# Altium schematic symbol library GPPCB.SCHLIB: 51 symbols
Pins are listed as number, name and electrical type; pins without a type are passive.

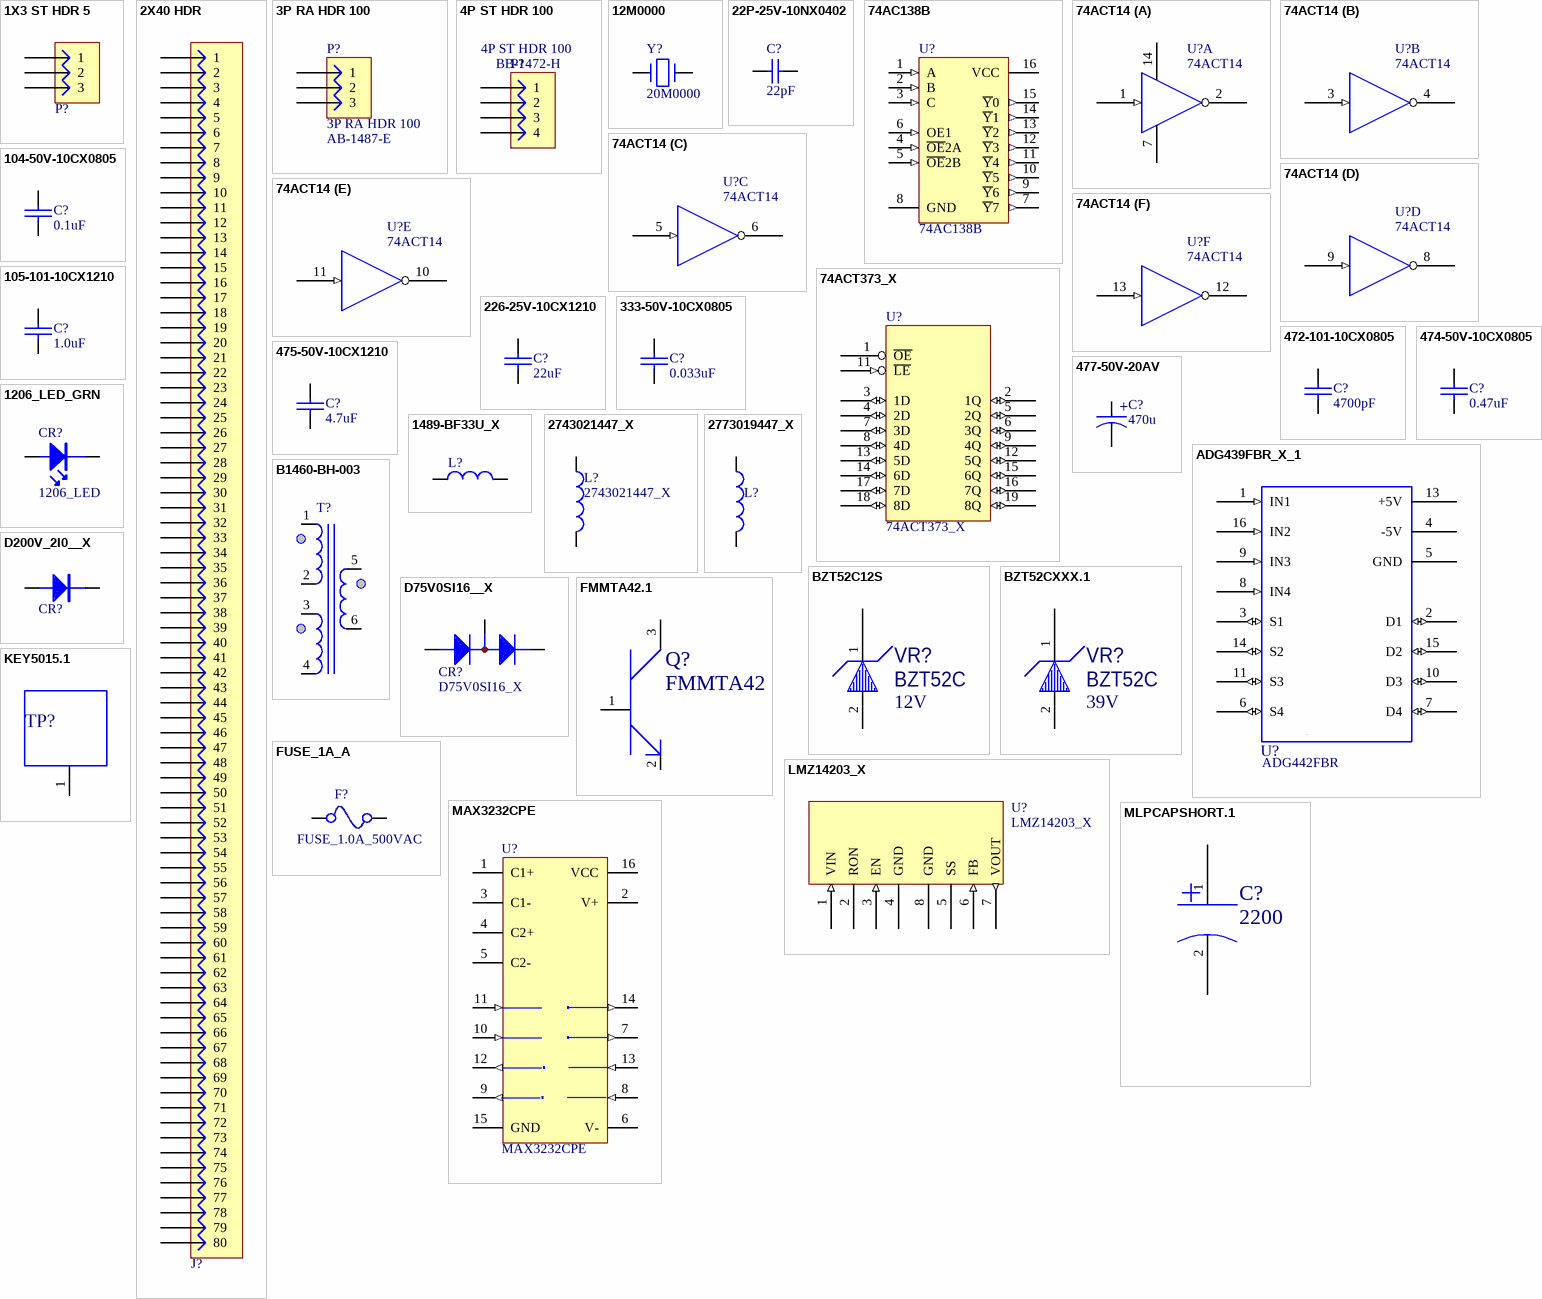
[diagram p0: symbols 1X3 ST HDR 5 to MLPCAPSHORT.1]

## 1X3 ST HDR 5
designator P?  (value not drawn)
HEADER, 3 PIN, ST, 5mm CTRS; AREA: 0.475
footprint H(JV01) (3P 30A ST PCB FEMALE)
pins: 1, 2, 3

## 2X40 HDR
designator J?  (value not drawn)
HEADER, 80 PIN; NAME: 80 PIN HEADER
footprint H2X40 (Footprint not found)
pins: 1, 2, 3, 4, 5, 6, 7, 8, 9, 10, 11, 12, 13, 14, 15, 16, 17, 18, 19, 20, 21, 22, 23, 24, 25, 26, 27, 28, 29, 30, 31, 32, 33, 34, 35, 36, 37, 38, 39, 40, 41, 42, 43, 44, 45, 46, 47, 48, 49, 50, 51, 52, 53, 54, 55, 56, 57, 58, 59, 60, 61, 62, 63, 64, 65, 66, 67, 68, 69, 70, 71, 72, 73, 74, 75, 76, 77, 78, 79, 80

## 3P RA HDR 100
designator P?  AMETEK PART NO: AB-1487-E  (hidden comment: 3P RA HDR 100)
HEADER, 3 PIN, RA, 0.100 CTRS; AREA: 0.15; DESIGNER: GTN 3/20/08
footprint H3RA100
pins: 1, 2, 3

## 4P ST HDR 100
designator P?  AMETEK PART NO: BB-1472-H  (hidden comment: 4P ST HDR 100)
HEADER, 4 PIN, ST, 0.100 CTRS
footprint SIP4
pins: 1, 2, 3, 4

## 12M0000
designator Y?, comment 20M0000
12.0000 MHZ XTAL; AMETEK PART NO: CB-1535-S; AMETEK DESCRIPTION: 12M0000
footprint XTAL3_I (XTAL_CC7V-T1A)
pins: 1, 2

## 22P-25V-10NX0402
designator C?  value 22pF  (hidden comment: 22P-25V-10NX0402)
CAP CERAMIC 22PF 25V 10% COG 0402; AMETEK PART NO: B1605-082; AREA: 0.0017; CHECKER: RSK 8/7/13; DESIGNER: GTN  10/31/11
footprint 0402/0.6/N (0402/N to 0402/0.6/N)
pins: 1, 2
1 alternate drawing of the same symbol

## 74AC138B
designator U?
3-to-8 Line Decoder Inverting
footprint DIP16 (DIP; 16 Leads; Row Spacing 7.62 mm; Pitch 2.54 mm)
3D model DIP16 (DIP; 16 Leads; Row Spacing 7.62 mm; Pitch 2.54 mm)
signal-integrity model 74AC138B
pins: 1 A (in), 2 B (in), 3 C (in), 4 ~{OE}2A (in), 5 ~{OE}2B (in), 6 OE1 (in), 7 ~{Y}7 (out), 8 GND (power), 9 ~{Y}6 (out), 10 ~{Y}5 (out), 11 ~{Y}4 (out), 12 ~{Y}3 (out), 13 ~{Y}2 (out), 14 ~{Y}1 (out), 15 ~{Y}0 (out), 16 VCC (power)

## 74ACT14
designator U?
IC, CMOS HEX INVERTER , DIP14; AMETEK PART NO: AB-1503-G; AREA: .263; DESIGNER: LEGACY PART 2/9/04 GTN
footprint DIP14
part A pins: 1 (in), 2, 7 (power), 14 (power)
part B pins: 3 (in), 4
part C pins: 5 (in), 6
part D pins: 8, 9 (in)
part E pins: 10, 11 (in)
part F pins: 12, 13 (in)

## 74ACT373_X
designator U?
IC, LATCH, OCTAL TRANSPARENT, TRISTATE; AMETEK PART NO: B1579-JP-001; AREA: 0.240; CHECKER: LEGACY PART
footprint SOL-20/N
pins: 1 ~{OE}, 2 1Q (io), 3 1D (io), 4 2D (io), 5 2Q (io), 6 3Q (io), 7 3D (io), 8 4D (io), 9 4Q (io), 10 GND (power) hidden, 11 ~{LE} (in), 12 5Q (io), 13 5D (io), 14 6D (io), 15 6Q (io), 16 7Q (io), 17 7D (io), 18 8D (io), 19 8Q (io), 20 VCC (power) hidden

## 104-50V-10CX0805
designator C?  value 0.1uF  (hidden comment: 104-50V-10CX0805)
CAPACITOR, CERAMIC, 0.1UF, 10%, X7R, 50V, 0805; AMETEK PART NO: B1605-029; AREA: 0.0066; TOLERANCE: 10; TYPE: CAP_X; CHECKER: GRL 5/20/02; DESIGNER: GTN 3/15/03
signal-integrity model Capacitor
simulation model Capacitor
footprint 0805/1.3/N (0805/N to 0805/1.3/N)
pins: 1, 2

## 105-101-10CX1210
designator C?  value 1.0uF  (hidden comment: 105-101-10CX1210)
CAPACITOR, CERAMIC, 1.0UF 10%, X7R, 100V, 2.7mm; AREA: 0.0174; TOLERANCE: 10; TYPE: CAP_X
signal-integrity model Capacitor
simulation model Capacitor
footprint 1210/2.8/N (1210N to 1210/2.8/N)
pins: 1, 2

## 226-25V-10CX1210
designator C?  value 22uF  (hidden comment: 226-25V-10CX1210)
CAPACITOR, CERAMIC, 22UF 10%, X7R, 25V, 1210; AREA: 0.0174; TOLERANCE: 10; TYPE: CAP_X
signal-integrity model Capacitor
simulation model Capacitor
footprint 1210/2.8/N (1210N to 1210/2.8/N)
pins: 1, 2

## 333-50V-10CX0805
designator C?  value 0.033uF  (hidden comment: 333-50V-10CX0805)
CAPACITOR, CERAMIC, 0.033UF 10%, X7R, 50V, 0805; AREA: 0.0066; TOLERANCE: 10; TYPE: CAP_X
signal-integrity model Capacitor
simulation model Capacitor
footprint 0805/1.3/N (0805/N to 0805/1.3/N)
pins: 1, 2

## 472-101-10CX0805
designator C?  value 4700pF  (hidden comment: 472-101-10CX0805)
CAPACITOR, CERAMIC, 4700PF 10%, X7R, 100V; AREA: 0.0066; TOLERANCE: 10; TYPE: CAP_X
signal-integrity model Capacitor
simulation model Capacitor
footprint 0805/1.3/N (0805/N to 0805/1.3/N)
pins: 1, 2

## 474-50V-10CX0805
designator C?  value 0.47uF  (hidden comment: 474-50V-10CX0805)
CAPACITOR, CERAMIC, 0.47UF 10%, X7R, 50V, 0805; AMETEK PART NO: B1605-063; AREA: 0.0066; TOLERANCE: 10; TYPE: CAP_X; CHECKER: CC 4/23/13; DESIGNER: GWL 8/5/05
signal-integrity model Capacitor
simulation model Capacitor
footprint 0805/1.4/N (0805/N to 0805/1.4/N)
pins: 1, 2

## 475-50V-10CX1210
designator C?  value 4.7uF  (hidden comment: 475-50V-10CX1210)
CAPACITOR, CERAMIC, 4.7UF 10%, X7R, 50V, 1210; AREA: 0.0174; TOLERANCE: 10; TYPE: CAP_X
signal-integrity model Capacitor
simulation model Capacitor
footprint 1210/2.8/N (1210N to 1210/2.8/N)
pins: 1, 2

## 477-50V-20AV
designator C?  value 470u  (hidden comment: 477-50V-20AV)
CAPACITOR, ALUM ELECT, 470UF, 50V, 477-50V-20AV, -55C TO 105 C; TYPE: CAP
footprint RH+.2/.512/1
pins: 1, 2

## 1206_LED_GRN
designator CR?, comment 1206_LED
LED, GRN, SMT; AMETEK PART NO: O516-P-002; AREA: 0.0116; TYPE: LED_X; DESIGNER: GTN 4/25/02   GRL 5/2/02; AMETEK DESCRIPTION: 1206_LED_GRN
3D model 1206
footprint 1206D/K/NP
pins: 1 K, 2 A

## 1489-BF33U_X
designator L?, comment MSS1260  (value not drawn)
INDUCTOR, PWR, MSS1260; VENDOR: COILCRAFT; MFGRN: MSS1260-333MLD
footprint IND_MSS1260
pins: 1, 2
2 alternate drawings of the same symbol

## 2743021447_X
designator L?
INDUCTOR, BEAD, SMT, 25-300MHz (43 material); AMETEK PART NO: B1489-AE-001; AREA: 0.06; TYPE: CHOKE; DESIGNER: 5/4/07   GTN
footprint SM-118/295
pins: 1, 2

## 2773019447_X
designator L?  (value not drawn)
INDUCTOR, BEAD, SMT, < 50 MHz (73 material); AREA: 0.022; TYPE: CHOKE
footprint SM-118/157 (GTN 5/4/07)
pins: 1, 2

## ADG439FBR_X_1
designator U?, comment VENDOR PART NO: ADG442FBR  (hidden comment: ADG442)
IC, 8 channel,  Fault-Protected Analog Multiplexers; VENDOR: ANALOG DEVICES
footprint SO-16/N (SO-16/N GTN 2/13/08 / 3D MODEL ADDED 5/8/12,RSK 8/12/13)
pins: 1 IN1 (in), 2 D1 (io), 3 S1 (io), 4 -5V (power), 5 GND (power), 6 S4 (io), 7 D4 (io), 8 IN4 (in), 9 IN3 (in), 10 D3 (io), 11 S3 (io), 13 +5V (power), 14 S2 (io), 15 D2 (io), 16 IN2 (in)

## B1460-BH-003
designator T?  (value not drawn)
TRANSFORMER, 400V, 400HZ; TYPE: TRANSF; AREA: 1.014
footprint XFMR (BH03) (400V, 400HZ)
pins: 1, 2, 3, 4, 5, 6

## BZT52C12S
designator VR?, comment BZT52C  value 12V
PKG_TYPE: SOD-323; PREFIX: VR; DEVICE: BZT52C12S; GEOMETRY.HEIGHT: 1.35MIL; VENDOR: DIODES INC
footprint SOD323
pins: 1 A, 2 K
2 alternate drawings of the same symbol

## BZT52CXXX.1
designator VR?, comment BZT52C  value 39V
PKG_TYPE: SOD-123; PREFIX: VR; GEOMETRY.HEIGHT: 1.35MIL; VENDOR: DIODES INC; MFGRN: BZT52C39
footprint SOD323/NP (Footprint not found)
pins: 1 N, 2 P
2 alternate drawings of the same symbol

## D75V0SI16__X
designator CR?  (value not drawn)
DIODE,  DUAL, SERIES PAIR, 75V; CHECKER: GRL 5/19/03; DESIGNER: GTN 5/18/03; AREA: 0.0293; TYPE: DIODE_X
3D model SOT-23
footprint SOT-23/N (SOT95P240-3N)
pins: 1 A, 2 K, 3 KA

## D200V_2I0__X
designator CR?  (value not drawn)
DIODE, RECTIFIER, 200V, 2 AMP, SMA PACKAGE; AREA: 0.0302; TYPE: DIODE_X
footprint SMA/NP
pins: 1 K, 2 A

## FMMTA42.1
designator Q?, comment FMMTA42
LEVEL: STD; VENDOR: ZETEX; MFGRN: FFMTA42; PKG_TYPE: SOT23; GEOMETRY.HEIGHT: 45.00MIL
footprint SOT-23/N (SOT95P240-3N)
pins: 1 B, 2 E, 3 C
2 alternate drawings of the same symbol

## FUSE_1A_A
designator F?, comment FUSE_1.0A_500VAC
FUSE, AXIAL LEADED, 1A, 500VAC; AMETEK PART NO: B1548-J-002; AREA: 0.228; TYPE: MISC; DESIGNER: CC; AMETEK DESCRIPTION: FUSE_1A_A
footprint AX1.05/.228 (15A FUSE  GTN 2/8/08)
pins: 1, 2

## KEY5015.1
designator TP?, comment KEY5015  (value not drawn)
VENDOR: KEYSTONE; MFGRN: 5015; LEVEL: STD; GEOMETRY.HEIGHT: 62.99MIL
footprint KS5015_TP_X (Footprint not found)
pins: 1 A
2 alternate drawings of the same symbol

## LMZ14203_X
designator U?
3A POWER MODULE, 42V MAX; AREA: 0.228
footprint TO-PMOD-7 (TO-PMOD-7, TZA07A 7 PIN PACKAGE WITH HEAT SINK PAD)
pins: 1 VIN (in), 2 RON, 3 EN (in), 4 GND (power), 5 SS, 6 FB (in), 7 VOUT (out), 8 GND (power)

## MAX3232CPE
designator U?
3.0V TO 5.5V, Low-Power, up to 1Mbps, True RS-232 Transceiver Using Four 0.1µF External Capacitor
footprint DIP-18 (DIP; 18 Leads; Row Spacing 7.62 mm; Pitch 2.54 mm)
3D model PE16 (DIP, 16-Pin, Row Spacing 7.62 mm, Pitch 2.54 mm)
pins: 1 C1+, 2 V+ (power), 3 C1-, 4 C2+, 5 C2-, 6 V- (power), 7 T2OUT (out), 8 R2IN (in), 9 R2OUT (out), 10 T2IN (in), 11 T1IN (in), 12 R1OUT (out), 13 R1IN (in), 14 T1OUT (out), 15 GND (power), 16 VCC (power)

## MLPCAPSHORT.1
designator C?, comment value 2200  (hidden comment: MLPCAPSHORT)
VENDOR: CORNELL-DUBILIER; MFGRN: MLP222M063EK0A; LEVEL: STD; GEOMETRY.HEIGHT: 500.00MIL
footprint CAP_MLP222M063EK0A
pins: 1 N1, 2 N2
2 alternate drawings of the same symbol

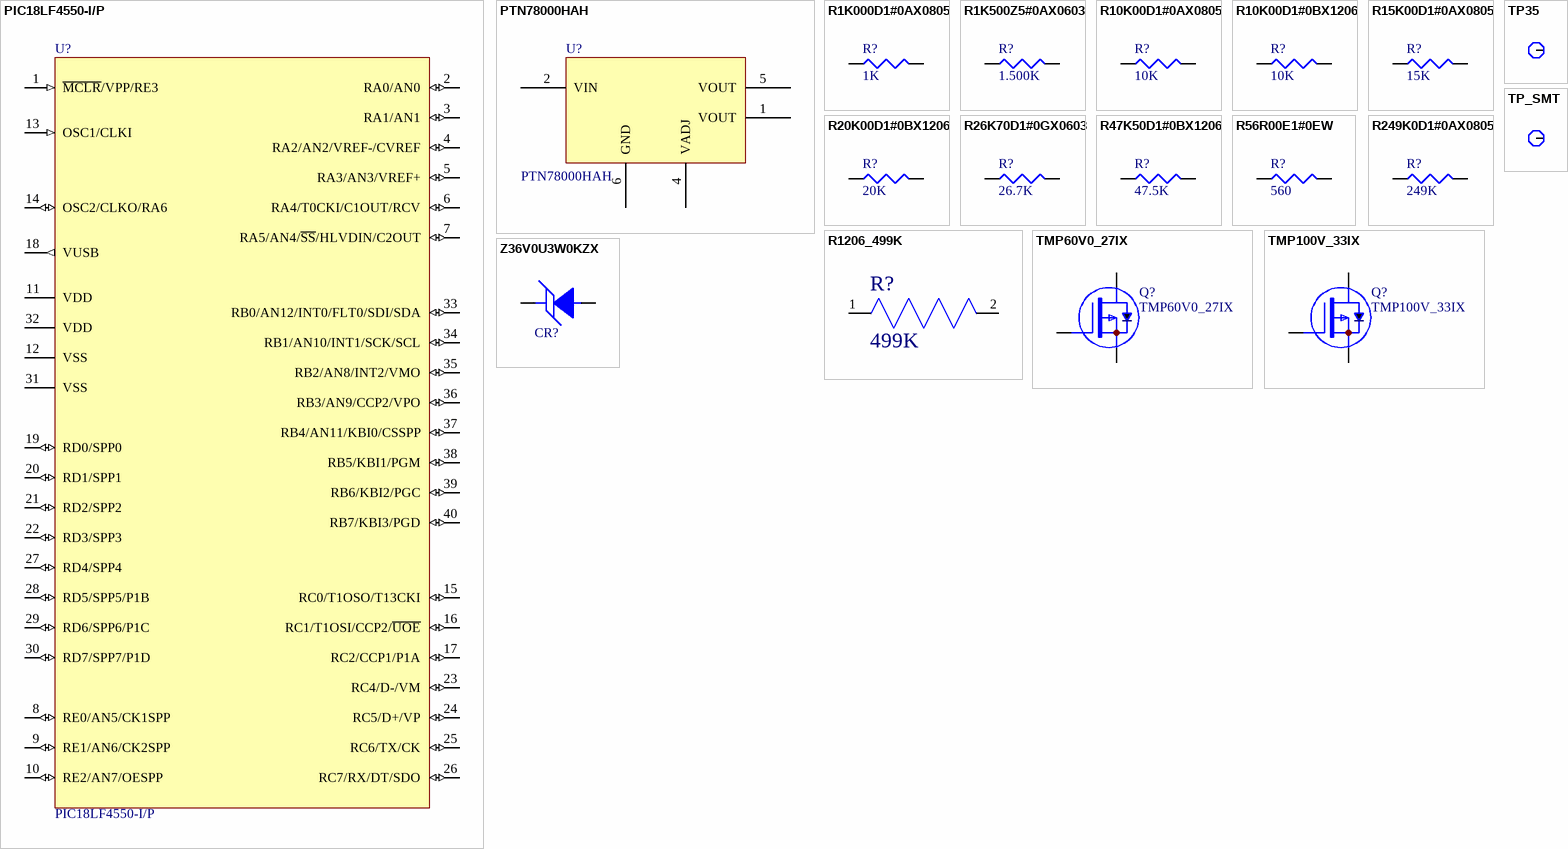
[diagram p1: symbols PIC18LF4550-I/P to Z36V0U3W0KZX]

## PIC18LF4550-I/P
designator U?
High Performance, Enhanced Flash, USB Microcontroller with nanoWatt Technology, 32K Flash, 40-Pin PDIP, Industrial Temperature Range
footprint DIP40 (DIP; 40)
pins: 1 ~{MCLR}/VPP/RE3 (in), 2 RA0/AN0 (io), 3 RA1/AN1 (io), 4 RA2/AN2/VREF-/CVREF (io), 5 RA3/AN3/VREF+ (io), 6 RA4/T0CKI/C1OUT/RCV (io), 7 RA5/AN4/~{SS}/HLVDIN/C2OUT (io), 8 RE0/AN5/CK1SPP (io), 9 RE1/AN6/CK2SPP (io), 10 RE2/AN7/OESPP (io), 11 VDD (power), 12 VSS (power), 13 OSC1/CLKI (in), 14 OSC2/CLKO/RA6 (io), 15 RC0/T1OSO/T13CKI (io), 16 RC1/T1OSI/CCP2/~{UOE} (io), 17 RC2/CCP1/P1A (io), 18 VUSB (out), 19 RD0/SPP0 (io), 20 RD1/SPP1 (io), 21 RD2/SPP2 (io), 22 RD3/SPP3 (io), 23 RC4/D-/VM (io), 24 RC5/D+/VP (io), 25 RC6/TX/CK (io), 26 RC7/RX/DT/SDO (io), 27 RD4/SPP4 (io), 28 RD5/SPP5/P1B (io), 29 RD6/SPP6/P1C (io), 30 RD7/SPP7/P1D (io), 31 VSS (power), 32 VDD (power), 33 RB0/AN12/INT0/FLT0/SDI/SDA (io), 34 RB1/AN10/INT1/SCK/SCL (io), 35 RB2/AN8/INT2/VMO (io), 36 RB3/AN9/CCP2/VPO (io), 37 RB4/AN11/KBI0/CSSPP (io), 38 RB5/KBI1/PGM (io), 39 RB6/KBI2/PGC (io), 40 RB7/KBI3/PGD (io)

## PTN78000HAH
designator U?
MODULE, 11.85V - 22V SWITCHING REGULATOR (1.5A); AREA: 0.42
footprint R_PDSS_T5 (THRU-HOLE)
pins: 1 VOUT (power), 2 VIN (power), 3 INH hidden, 4 VADJ, 5 VOUT (power), 6 GND (power)

## R1K000D1#0AX0805
designator R?  value 1K  (hidden comment: R1K000D1#0AX0805)
RESISTOR, 1K, 1%, 100 PPM, 0805; AREA: 0.0085; TOLERANCE: 1
signal-integrity model RESISTOR
simulation model RESISTOR
footprint 0805/N (RESC2012N)
pins: 1, 2

## R1K500Z5#0AX0603
designator R?  value 1.500K  (hidden comment: R1K500Z5#0AX0603)
RESISTOR, 1.500K OHM, 5%, 200 PPM, 0603; AREA: 0.0055; TOLERANCE: 5
signal-integrity model RESISTOR
simulation model RESISTOR
footprint 0603/N (RESC1608X50N)
pins: 1, 2

## R10K00D1#0AX0805
designator R?  value 10K  (hidden comment: R10K00D1#0AX0805)
RESISTOR, 10K OHM, 1%, 100 PPM, 0805; AREA: 0.0085; TOLERANCE: 1
signal-integrity model RESISTOR
simulation model RESISTOR
footprint 0805/N
pins: 1, 2

## R10K00D1#0BX1206
designator R?  value 10K  (hidden comment: R10K00D1#0BX1206)
RESISTOR, 10K, 1%, 100 PPM, 1206; AREA: 0.0116; TOLERANCE: 1
signal-integrity model RESISTOR
simulation model RESISTOR
footprint 1206/N (RESC3216N)
pins: 1, 2

## R15K00D1#0AX0805
designator R?  value 15K  (hidden comment: R15K00D1#0AX0805)
RESISTOR, 15K, 1%, 100 PPM, 0805; AREA: 0.0066; TOLERANCE: 1
3D model 0805
signal-integrity model RESISTOR
simulation model RESISTOR
footprint 0805/N
3D model 0805 (PCB3D Model)
pins: 1, 2

## R20K00D1#0BX1206
designator R?  value 20K  (hidden comment: R20K00D1#0BX1206)
RESISTOR, 20K, 1%, 100 PPM, 1206; AREA: 0.0116; TOLERANCE: 1
signal-integrity model RESISTOR
simulation model RESISTOR
footprint 1206/N (RESC3216N)
pins: 1, 2

## R26K70D1#0GX0603
designator R?  value 26.7K  (hidden comment: R26K70D1#0GX0603)
RESISTOR, 26.7K OHM, 1%, 100 PPM, 0603; AREA: 0.0055; TOLERANCE: 1
signal-integrity model RESISTOR
simulation model RESISTOR
footprint 0603/N
pins: 1, 2

## R47K50D1#0BX1206
designator R?  value 47.5K  (hidden comment: R47K50D1#0BX1206)
RESISTOR, THIN FILM 47.5K, 0.1%, 100 PPM, 1206; AREA: 0.0116; TOLERANCE: .1
signal-integrity model RESISTOR
simulation model RESISTOR
footprint 1206/N
pins: 1, 2

## R56R00E1#0EW
designator R?  value 560  (hidden comment: R56R00E1#0EW)
RESISTOR, 56 OHMS, 1%, 20PPM, SILICONE-CERAMIC WIREWOUND; AMETEK PART NO: B1604-H-002; AREA: 0.11; DESIGNER: GRL 8/17/05
3D model RN55(400)
footprint AX.55/.125L (Standard part formed with long leads)
pins: 1, 2

## R249K0D1#0AX0805
designator R?  value 249K  (hidden comment: R249K0D1#0AX0805)
RESISTOR, 249K OHMS, 1%, 0805; AMETEK PART NO: B1604-097; AREA: 0.0085; TOLERANCE: 1; DESIGNER: GRL 12/09/03
signal-integrity model RESISTOR
simulation model RESISTOR
footprint 0805/N
pins: 1, 2

## R1206_499K
designator R?  value 499K  (hidden comment: R1206_499K)
Resistor, General Purpose, 47.5K, 1%, 100 PPM, 1206; LEVEL: STD; PKG_TYPE: R1206; GEOMETRY.HEIGHT: 70.87MIL; VENDOR: PANASONIC; MFGRN: ERJ-8ENF4993V
footprint 1206/N (RESC3216N)
pins: 1 N1, 2 N2
2 alternate drawings of the same symbol

## TMP60V0_27IX
designator Q?
POWER MOSFET, P-CHANNEL, 60V, 27A, D2PAK; TYPE: TRANS_X
footprint D2PAK4/N (TO-263AB 4 PINS)
pins: 1 G, 3 S, 4 D

## TMP100V_33IX
designator Q?
POWER MOSFET, P-CHANNEL, 100V, 33A, D2PAK; TYPE: TRANS_X
footprint D2PAK4/N (TO-263AB 4 PINS)
pins: 1 G, 3 S, 4 D

## TP35
designator TP?, comment TP_SMT  (value not drawn)
TEST POINT, 0.035 dia Oct pad w/ 0.010 hole, or SMT; AREA: 0.0012
footprint TP35 (0.035 dia testpoint)
footprint TP_SMT (0.035 DIA., OCTAGONAL, SMT - fixed Paste 10/11/12)
pins: 1 TP "TESTPOINT"

## TP_SMT
designator TP?, comment TP_30  (value not drawn)
AREA: 0.0012
footprint TP_30 (Ametek_testpoint)
pins: 1 TP "TESTPOINT"

## Z36V0U3W0KZX
designator CR?  (value not drawn)
DIODE, ZENER, 36V, DO214AB+; AREA: 0.088; TYPE: DIODE_X
footprint DO-214AB+/NP (DIOM7959X265N ( SMB)     GTN 9/25/06)
pins: 1 K, 2 A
